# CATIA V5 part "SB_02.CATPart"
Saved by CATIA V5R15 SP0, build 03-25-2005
Part number: SB_02
Material "Pastel Green": density 7860 kg/m3, Young's modulus 2e+11 Pa, Poisson ratio 0.266
Bounding box of the stored display mesh (mm): x 0 to 79, y 0 to 158, z 0 to 49.2
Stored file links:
  E:\#01 CATIA Lecture Materials\#06 DMU\#11 DMU Page01 KIN EX11\SB_02.CATPart
  C:\Program Files\Dassault Systemes\B20\win_b64\startup\materials\Catalog.CATMaterial
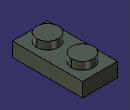
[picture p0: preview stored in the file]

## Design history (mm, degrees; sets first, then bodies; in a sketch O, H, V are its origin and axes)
Body1 (main body), material "Pastel Green"
  Sketch1 on xy-plane, origin (0, 0, 0), H (1, 0, 0), V (0, 1, 0)
    circle A1 centre (39.5, 39.5) radius 24.5
    point P1 (39.5, 39.5)
    radius A1 = 24.5
    distance P1 H = 39.5
    distance P1 V = 39.5
  Pad1: profile Sketch1, direction (0, 0, 1), length 49.2
  RectPattern1: of Pad1, direction 1 instances 2, spacing 79, along yz-plane
  Sketch2 on xy-plane, origin (0, 0, 0), H (1, 0, 0), V (0, 1, 0)
    point P1 (0, 158)
    line L1 (0, 158) -> (79, 158)
    line L2 (79, 158) -> (79, 0)
    line L3 (79, 0) -> (0, 0)
    line L4 (0, 0) -> (0, 158)
    point P3 (79, 0)
    distance L2 L4 = 79
    distance L1 L3 = 158 {= RectPattern1.Nb1 * 79mm}
    coincidence: P1 V, P3 H
    horizontal: L1 H, L3 H
    vertical: L2 V, L4 V
  Pad2: profile Sketch2, direction (0, 0, 1), length 32
  Shell1: ExtOffset 0, Face face of Pad2, IntOffset 15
